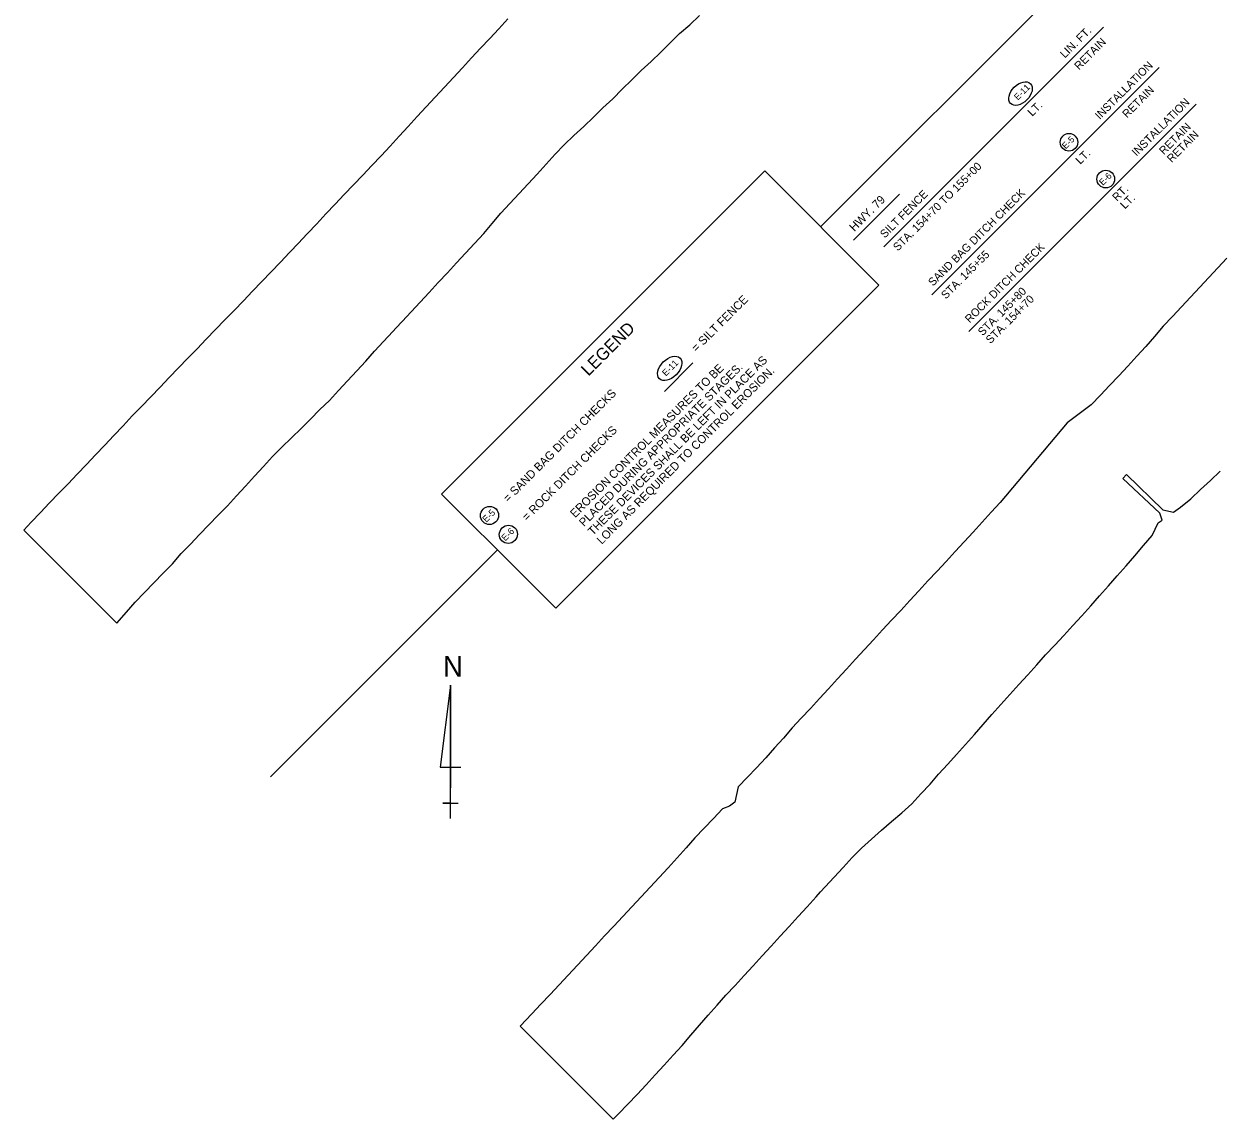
# Model space of a CAD drawing. Extents: x 1377291 to 1378879, y 1932405 to 1934097.
# Drawn here: x 1377291 to 1378187, y 1932405 to 1933226 of the extents above; entities that cross this region are included whole.
import ezdxf

# ---------------------------------------------------------------- set-up
doc = ezdxf.new("R2010")
doc.units = 0
for name, color, linetype in [('1', 7, 'Continuous'), ('44', 7, 'Continuous'), ('63', 7, 'Continuous'), ('Level 1', 7, 'Continuous'), ('Level 44', 7, 'Continuous'), ('R_NO PLOT', 7, 'Continuous')]:
    doc.layers.add(name, color=color, linetype=linetype)

msp = doc.modelspace()

# ---------------------------------------------------------------- linework, layer by layer
at = {"layer": '1'}
for p, q in [((1377887.91, 1933073.76), (1378090.27, 1933276.12)), ((1377603.69, 1932873.39), (1377845.99, 1933115.68)), ((1377931.59, 1933030.09), (1377845.99, 1933115.68)), ((1377665.3, 1932811.78), (1377603.69, 1932873.39)), ((1377475.54, 1932661.38), (1377645.62, 1932831.46))]:
    msp.add_line(p, q, dxfattribs=at)
msp.add_lwpolyline([(1377665.3, 1932811.78), (1377689.29, 1932787.79), (1377931.59, 1933030.09)], dxfattribs=at)
for centre in [(1378074.11, 1933137.17), (1378101.68, 1933109.59)]:
    msp.add_circle(centre, 6.61, dxfattribs=at)
msp.add_ellipse((1378037.76, 1933173.7), major_axis=(7.44, 7.44), ratio=0.638788, dxfattribs=at)
at = {"layer": '44'}
for p, q in [((1377935.29, 1933058.9), (1378099.9, 1933223.51)), ((1377971.38, 1933022.81), (1378141.8, 1933193.22)), ((1377998.96, 1932995.23), (1378169.38, 1933165.65)), ((1377912.46, 1933063.79), (1377947, 1933098.32))]:
    msp.add_line(p, q, dxfattribs=at)
at = {"layer": '63'}
for p, q in [((1377610.45, 1932730.07), (1377602.76, 1932668.53)), ((1377610.45, 1932630.07), (1377610.45, 1932730.07)), ((1377610.45, 1932730.07), (1377610.45, 1932653.14)), ((1377602.76, 1932668.53), (1377618.14, 1932668.53)), ((1377610.45, 1932630.07), (1377610.45, 1932653.14)), ((1377610.45, 1932641.61), (1377604.68, 1932641.61)), ((1377604.68, 1932641.61), (1377616.22, 1932641.61)), ((1377610.45, 1932630.07), (1377610.45, 1932641.61))]:
    msp.add_line(p, q, dxfattribs=at)
at = {"layer": 'Level 1'}
for centre, major_axis, ratio in [((1377774.81, 1932967.61), (7.75, 7.75), 0.622952), ((1377639.7, 1932857.32), (-4.87, -4.86), 0.97521), ((1377653.84, 1932843.17), (-4.87, -4.86), 0.97521)]:
    msp.add_ellipse(centre, major_axis=major_axis, ratio=ratio, dxfattribs=at)
at = {"layer": 'Level 44'}
msp.add_lwpolyline([(1377770.76, 1932950.36), (1377792.05, 1932971.67)], dxfattribs=at)
at = {"layer": 'R_NO PLOT'}
for points in [[(1377653.52, 1933229.64), (1377646.7, 1933222.33), (1377639.87, 1933215.02), (1377633.03, 1933207.72), (1377626.15, 1933200.47), (1377619.4, 1933193.09), (1377612.64, 1933185.72), (1377605.83, 1933178.4), (1377599.01, 1933171.08), (1377592.2, 1933163.76), (1377585.38, 1933156.45), (1377578.63, 1933149.06), (1377571.88, 1933141.69), (1377565.1, 1933134.34), (1377558.36, 1933126.95), (1377551.52, 1933119.65), (1377544.62, 1933112.41), (1377537.71, 1933105.19), (1377530.81, 1933097.94), (1377523.9, 1933090.72), (1377517.08, 1933083.41), (1377510.25, 1933076.1), (1377503.32, 1933068.89), (1377499.19, 1933064.42), (1377496.67, 1933061.69), (1377489.82, 1933054.41), (1377482.91, 1933047.18), (1377475.98, 1933039.96), (1377469.05, 1933032.76), (1377462.12, 1933025.55), (1377455.19, 1933018.34), (1377448.25, 1933011.13), (1377441.31, 1933003.94), (1377434.34, 1932996.76), (1377427.39, 1932989.57), (1377420.43, 1932982.39), (1377413.46, 1932975.21), (1377406.57, 1932967.97), (1377399.63, 1932960.76), (1377392.71, 1932953.55), (1377385.78, 1932946.34), (1377378.85, 1932939.13), (1377371.92, 1932931.92), (1377365.04, 1932924.66), (1377358.16, 1932917.4), (1377351.28, 1932910.14), (1377344.4, 1932902.89), (1377337.52, 1932895.63), (1377330.63, 1932888.38), (1377323.72, 1932881.16), (1377316.82, 1932873.92), (1377309.92, 1932866.68), (1377303.02, 1932859.44), (1377296.16, 1932852.17), (1377290.65, 1932846.27), (1377360.26, 1932776.66)], [(1377360.26, 1932776.66), (1377367.53, 1932784.82), (1377374.14, 1932792.33), (1377381.08, 1932799.53), (1377388.06, 1932806.69), (1377394.95, 1932813.94), (1377401.99, 1932821.04), (1377408.45, 1932828.7), (1377415.42, 1932835.88), (1377422.37, 1932843.06), (1377429.34, 1932850.24), (1377436.3, 1932857.42), (1377443.23, 1932864.63), (1377449.96, 1932872.03), (1377456.8, 1932879.32), (1377463.54, 1932886.71), (1377470.34, 1932894.05), (1377477.09, 1932901.42), (1377484.08, 1932908.57), (1377491.3, 1932915.51), (1377498.44, 1932922.53), (1377505.51, 1932929.6), (1377512.57, 1932936.69), (1377519.75, 1932943.66), (1377526.5, 1932951.04), (1377533.34, 1932958.34), (1377540.14, 1932965.67), (1377546.86, 1932973.08), (1377553.51, 1932980.55), (1377560.32, 1932987.88), (1377567.12, 1932995.21), (1377569.67, 1932997.91), (1377574.1, 1933002.7), (1377580.93, 1933010), (1377587.7, 1933017.36), (1377594.55, 1933024.65), (1377601.32, 1933032.01), (1377608.09, 1933039.37), (1377614.88, 1933046.71), (1377621.68, 1933054.04), (1377628.5, 1933061.36), (1377635.32, 1933068.67), (1377641.8, 1933076.3), (1377648.28, 1933083.93), (1377655.02, 1933091.32), (1377661.81, 1933098.66), (1377668.58, 1933106.02), (1377675.34, 1933113.39), (1377682.06, 1933120.8), (1377688.81, 1933128.18), (1377695.77, 1933135.36), (1377702.99, 1933142.3), (1377710.35, 1933149.11), (1377717.6, 1933156.02), (1377724.74, 1933163.04), (1377732.11, 1933169.83), (1377739.19, 1933176.91), (1377746.26, 1933183.98), (1377753.32, 1933191.08), (1377760.78, 1933197.78), (1377768.03, 1933204.7), (1377775.05, 1933211.83), (1377782.19, 1933218.84), (1377789.97, 1933225.25), (1377797.07, 1933232.31)], [(1378192.54, 1933050.39), (1378185.72, 1933043.08), (1378178.91, 1933035.76), (1378172.1, 1933028.44), (1378165.27, 1933021.13), (1378158.46, 1933013.81), (1378151.63, 1933006.5), (1378144.82, 1932999.18), (1378138.23, 1932991.65), (1378131.61, 1932984.15), (1378124.96, 1932976.68), (1378118.32, 1932969.19), (1378111.47, 1932961.91), (1378104.54, 1932954.7), (1378097.62, 1932947.48), (1378090.7, 1932940.26), (1378072.85, 1932926.84), (1378022.54, 1932867.08), (1378015.77, 1932859.72), (1378009.08, 1932852.28), (1378002.36, 1932844.88), (1377995.55, 1932837.56), (1377988.76, 1932830.21), (1377981.99, 1932822.86), (1377975.22, 1932815.49), (1377968.4, 1932808.18), (1377961.61, 1932800.83), (1377954.81, 1932793.51), (1377948.01, 1932786.17), (1377941.15, 1932778.89), (1377934.4, 1932771.51), (1377927.63, 1932764.15), (1377920.75, 1932756.9), (1377913.96, 1932749.56), (1377907.29, 1932742.1), (1377900.52, 1932734.74), (1377893.8, 1932727.33), (1377886.98, 1932720.02), (1377880.2, 1932712.67), (1377873.44, 1932705.3), (1377866.62, 1932697.99), (1377860.16, 1932690.33), (1377853.38, 1932682.98), (1377846.77, 1932675.47), (1377839.93, 1932668.18), (1377833, 1932660.97), (1377826.07, 1932653.75), (1377823.53, 1932642.42), (1377819.61, 1932639.3), (1377814.39, 1932637.29), (1377807.49, 1932630.04), (1377800.58, 1932622.82), (1377793.73, 1932615.53), (1377787.1, 1932608.04), (1377780.47, 1932600.55), (1377773.72, 1932593.16), (1377766.91, 1932585.84), (1377760.1, 1932578.52), (1377753.29, 1932571.2), (1377746.48, 1932563.87), (1377739.65, 1932556.57), (1377732.81, 1932549.28), (1377725.97, 1932541.98), (1377719.13, 1932534.69), (1377712.34, 1932527.34), (1377705.55, 1932520), (1377698.75, 1932512.67), (1377691.96, 1932505.33), (1377685.15, 1932498), (1377678.25, 1932490.77), (1377671.34, 1932483.54), (1377662.55, 1932474.37), (1377732.28, 1932404.64)], [(1378144.48, 1932861.47), (1378152.37, 1932859.8), (1378157.78, 1932863.44), (1378165.57, 1932869.84), (1378172.81, 1932876.77), (1378180.26, 1932883.49), (1378187.46, 1932890.44)], [(1378140.97, 1932851.8), (1378143.9, 1932853.88), (1378142.2, 1932859.01), (1378114.41, 1932885.01), (1378117.1, 1932887.98), (1378144.48, 1932861.47)], [(1377732.28, 1932404.64), (1377736.32, 1932408.7), (1377743.37, 1932415.8), (1377750.31, 1932423), (1377757.07, 1932430.37), (1377763.82, 1932437.75), (1377770.57, 1932445.13), (1377777.33, 1932452.5), (1377784, 1932459.95), (1377790.58, 1932467.5), (1377797.15, 1932475.04), (1377803.73, 1932482.58), (1377810.33, 1932490.1), (1377816.95, 1932497.6), (1377823.83, 1932504.86), (1377830.51, 1932512.3), (1377837.4, 1932519.55), (1377844.1, 1932526.98), (1377850.8, 1932534.4), (1377857.56, 1932541.78), (1377864.36, 1932549.11), (1377871.06, 1932556.54), (1377877.83, 1932563.9), (1377884.57, 1932571.28), (1377887.94, 1932575.04), (1377891.25, 1932578.73), (1377898.07, 1932586.04), (1377904.89, 1932593.36), (1377911.49, 1932600.88), (1377918.68, 1932607.85), (1377926.17, 1932614.53), (1377933.67, 1932621.2), (1377941.16, 1932627.89), (1377948.84, 1932634.39), (1377956.4, 1932641.01), (1377963.04, 1932648.49), (1377969.95, 1932655.72), (1377976.36, 1932663.42), (1377983.17, 1932670.74), (1377989.89, 1932678.15), (1377996.52, 1932685.65), (1378003.17, 1932693.11), (1378009.78, 1932700.62), (1378016.36, 1932708.16), (1378023.01, 1932715.64), (1378029.73, 1932723.05), (1378036.43, 1932730.47), (1378043.17, 1932737.86), (1378049.9, 1932745.26), (1378056.58, 1932752.71), (1378063.38, 1932760.04), (1378070.14, 1932767.41), (1378076.9, 1932774.78), (1378083.68, 1932782.13), (1378090.43, 1932789.51), (1378097.06, 1932797), (1378103.64, 1932804.54), (1378110.26, 1932812.05), (1378116.87, 1932819.56), (1378123.41, 1932827.14), (1378129.97, 1932834.69), (1378136.47, 1932842.31), (1378140.97, 1932851.8)]]:
    msp.add_lwpolyline(points, dxfattribs=at)

# ---------------------------------------------------------------- texts
at = {"layer": '1'}
for s, rotation, p in [('E-11', 44.99998, (1378035.75, 1933168.35)), ('E-5 ', 45, (1378071.69, 1933131.8)), ('E-6 ', 45, (1378099.48, 1933104.44))]:
    msp.add_text(s, height=4.8, rotation=rotation, dxfattribs=at).set_placement(p)
at = {"layer": '44'}
for s, height, rotation, p in [('LIN. FT.', 6, 44.99998, (1378070.98, 1933199.9)), ('RETAIN', 6, 44.99998, (1378081.66, 1933191.07)), ('INSTALLATION', 6, 45, (1378097.17, 1933153.91)), ('RETAIN', 6, 45, (1378117.68, 1933155.05)), ('LT.', 6, 44.99998, (1378046.57, 1933156.22)), ('INSTALLATION', 6, 45, (1378124.75, 1933126.33)), ('RETAIN', 6, 45, (1378145.25, 1933127.47)), ('RETAIN', 6, 45, (1378151.14, 1933121.58)), ('LT.', 6, 45, (1378082.59, 1933120.2)), ('STA. 154+70 TO 155+00', 6, 44.99998, (1377945.76, 1933055.2)), ('RT.', 6, 45, (1378110.07, 1933092.52)), ('HWY. 79', 6.25, 45, (1377913.22, 1933069.88)), ('SILT FENCE      ', 6, 44.99998, (1377936.02, 1933064.94)), ('SAND BAG DITCH CHECK', 6, 45, (1377972.12, 1933028.85)), ('LT.', 6, 45, (1378116.06, 1933086.73)), ('ROCK DITCH CHECK', 6, 45, (1377999.69, 1933001.28)), ('STA. 145+55', 6, 45, (1377981.78, 1933019.18)), ('STA. 145+80', 6, 45, (1378009.36, 1932991.61)), ('STA. 154+70', 6, 45, (1378015.25, 1932985.72))]:
    msp.add_text(s, height=height, rotation=rotation, dxfattribs=at).set_placement(p)
at = {"layer": '63'}
msp.add_text('N', height=15.38, rotation=360, dxfattribs=at).set_placement((1377604.82, 1932736.48))
at = {"layer": 'Level 1'}
for s, height, p in [('= SILT FENCE', 6.25, (1377794.76, 1932979.39)), ('EROSION CONTROL MEASURES TO BE', 6.25, (1377703.86, 1932855.2)), ('PLACED DURING APPROPRIATE STAGES. ', 6.25, (1377710.51, 1932848.55)), ('THESE DEVICES SHALL BE LEFT IN PLACE AS ', 6.25, (1377717.16, 1932841.89)), ('E-11 ', 4.876, (1377771.98, 1932961.4)), ('LONG AS REQUIRED TO CONTROL EROSION.', 6.25, (1377723.82, 1932835.24)), ('= SAND BAG DITCH CHECKS', 6.25, (1377653.6, 1932866.79)), ('= ROCK DITCH CHECKS', 6.25, (1377667.74, 1932852.65)), ('E-5 ', 4.876, (1377637.28, 1932851.76)), ('E-6 ', 4.876, (1377651.52, 1932837.83))]:
    msp.add_text(s, height=height, rotation=45.00001, dxfattribs=at).set_placement(p)
at = {"layer": 'Level 44'}
msp.add_text('LEGEND', height=9.143, rotation=45.00001, dxfattribs=at).set_placement((1377713.88, 1932961.37))

doc.saveas('drawing.dxf')
